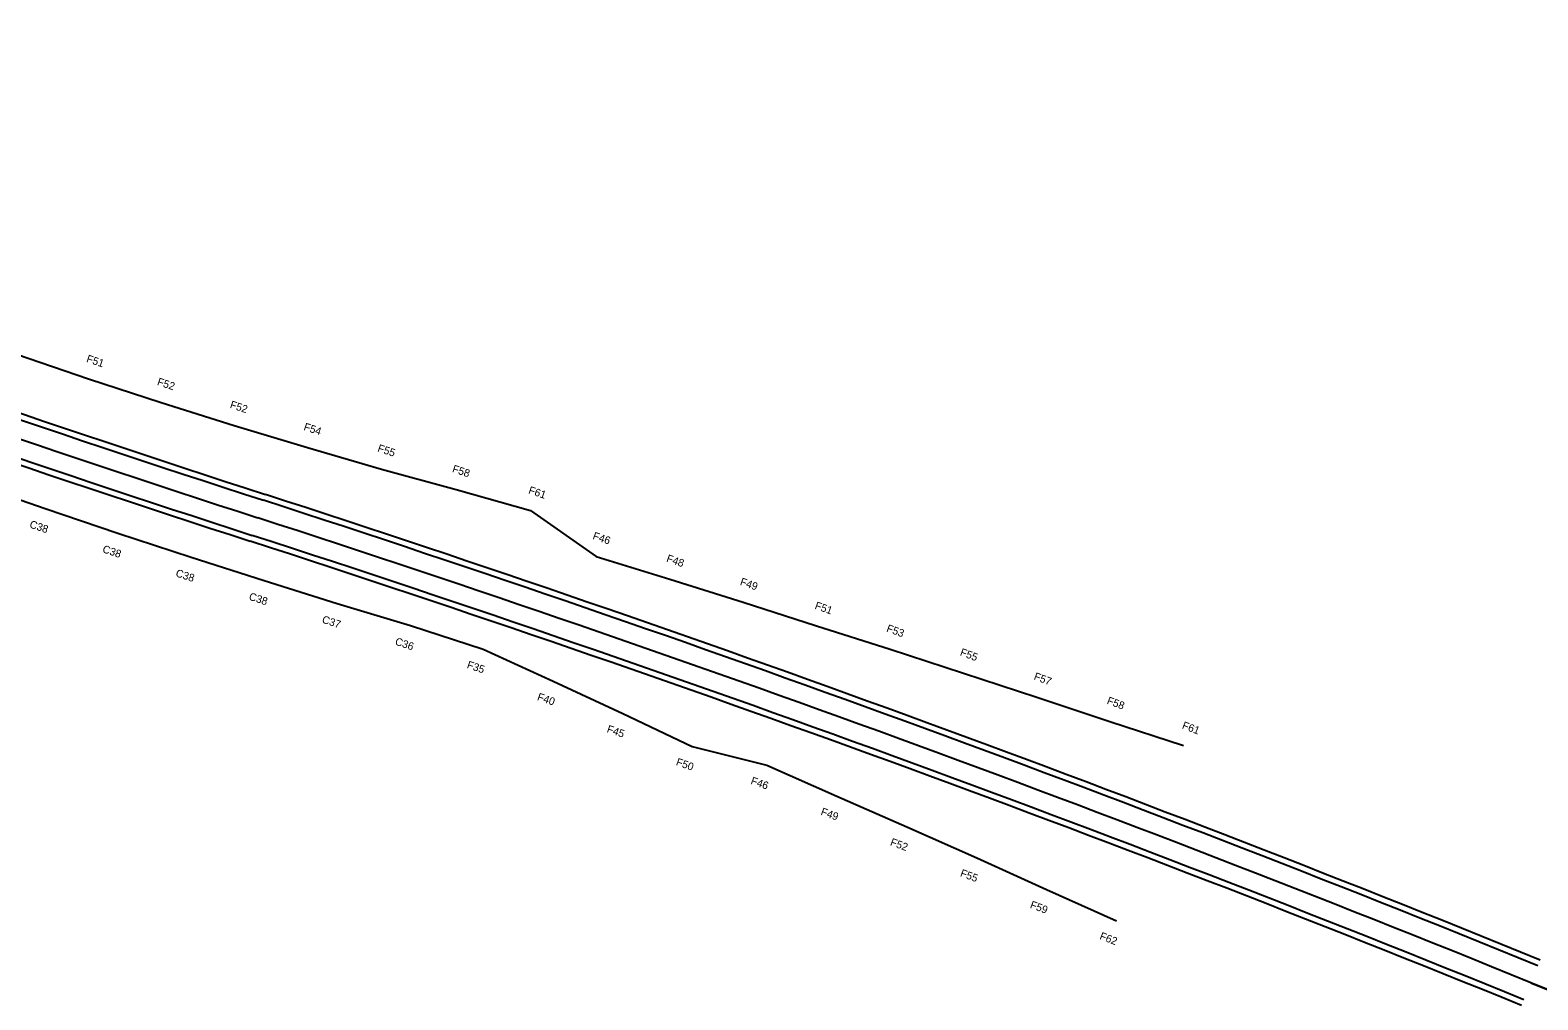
# Model space of a CAD drawing. Extents: x 2163527 to 2171930, y 206045 to 210376.
# Drawn here: x 2166437 to 2167420, y 208838 to 209469 of the extents above; entities that cross this region are included whole.
import ezdxf

# ---------------------------------------------------------------- set-up
doc = ezdxf.new("R2010")
doc.units = 0
for name, color, linetype in [('Default', 7, 'Continuous'), ('RD_PD_CstnLmt', 7, 'Continuous'), ('RD_PD_TX_CstnLmt', 7, 'Continuous')]:
    doc.layers.add(name, color=color, linetype=linetype)

msp = doc.modelspace()

# ---------------------------------------------------------------- linework, layer by layer
at = {"layer": 'Default'}
for p, q in [((2170316.55, 207666.95), (2167415.27, 208848.65)), ((2167415.27, 208848.65), (2170458.15, 207609.28))]:
    msp.add_line(p, q, dxfattribs=at)
for centre, radius, start, end in [((2170282.56, 220567.81), 11988, 247.838824, 252.056631), ((2170282.56, 220567.81), 11988, 247.838824, 252.056631), ((2170282.56, 220567.81), 11984, 247.838824, 252.056631), ((2170282.56, 220567.81), 12000, 247.838824, 252.056631), ((2170282.56, 220567.81), 12000, 247.838824, 252.056631), ((2170282.56, 220567.81), 12012, 247.838824, 252.056631), ((2170282.56, 220567.81), 12012, 247.838824, 252.056631), ((2170282.56, 220567.81), 12016, 247.838824, 252.056631), ((2162888.71, 197735.13), 12016, 67.838824, 72.056631), ((2162888.71, 197735.13), 12012, 67.838824, 72.056631), ((2162888.71, 197735.13), 12012, 67.838824, 72.056631), ((2162888.71, 197735.13), 12000, 67.838824, 72.056631), ((2162888.71, 197735.13), 12000, 67.838824, 72.056631), ((2162888.71, 197735.13), 11988, 67.838824, 72.056631), ((2162888.71, 197735.13), 11988, 67.838824, 72.056631), ((2162888.71, 197735.13), 11984, 67.838824, 72.056631)]:
    msp.add_arc(centre, radius, start, end, dxfattribs=at)
at = {"layer": 'RD_PD_CstnLmt'}
for p, q in [((2166428.26, 209258.13), (2166475.34, 209241.94)), ((2166475.34, 209241.94), (2166522.69, 209226.55)), ((2166522.69, 209226.55), (2166570.19, 209211.63)), ((2166570.19, 209211.63), (2166618.02, 209197.27)), ((2166618.02, 209197.27), (2166666.28, 209183.26)), ((2166666.28, 209183.26), (2166714.78, 209169.91)), ((2166399.6, 209174.02), (2166446.98, 209157.56)), ((2166714.78, 209169.91), (2166763.24, 209156.36)), ((2166446.98, 209157.56), (2166494.48, 209141.45)), ((2166763.24, 209156.36), (2166806.04, 209126.29)), ((2166494.48, 209141.45), (2166542.14, 209125.82)), ((2166542.14, 209125.82), (2166589.82, 209110.6)), ((2166806.04, 209126.29), (2166854.06, 209111.57)), ((2166589.82, 209110.6), (2166637.37, 209095.63)), ((2166854.06, 209111.57), (2166901.96, 209096.45)), ((2166637.37, 209095.63), (2166685.12, 209081.26)), ((2166901.96, 209096.45), (2166949.81, 209081.16)), ((2166685.12, 209081.26), (2166732.54, 209065.85)), ((2166949.81, 209081.16), (2166997.68, 209065.88)), ((2166732.54, 209065.85), (2166778.1, 209045.05)), ((2166997.68, 209065.88), (2167045.49, 209050.38)), ((2167045.49, 209050.38), (2167093.27, 209034.76)), ((2166778.1, 209045.05), (2166823.56, 209024.06)), ((2167093.27, 209034.76), (2167140.97, 209018.89)), ((2166823.56, 209024.06), (2166868.78, 209002.51)), ((2167140.97, 209018.89), (2167188.77, 209003.21)), ((2166868.78, 209002.51), (2166917.3, 208990.32)), ((2166917.3, 208990.32), (2166962.96, 208970.14)), ((2166962.96, 208970.14), (2167008.67, 208950.15)), ((2167008.67, 208950.15), (2167054.26, 208929.93)), ((2167054.26, 208929.93), (2167099.69, 208909.33)), ((2167099.69, 208909.33), (2167145.14, 208888.89))]:
    msp.add_line(p, q, dxfattribs=at)

# ---------------------------------------------------------------- texts
at = {"layer": 'RD_PD_TX_CstnLmt'}
for s, rotation, p in [('F51', 341.41981, (2166473.51, 209253.11)), ('F52', 341.65854, (2166519.62, 209238.11)), ('F52', 341.89727, (2166567.07, 209223.17)), ('F54', 341.97726, (2166615.11, 209208.74)), ('F55', 341.73852, (2166663.27, 209194.79)), ('F58', 341.49979, (2166711.91, 209181.42)), ('F61', 341.26106, (2166761.59, 209167.48)), ('C38', 341.41981, (2166436.41, 209145.28)), ('F46', 341.02233, (2166803.47, 209137.75)), ('C38', 341.65854, (2166483.96, 209129.13)), ('F48', 340.78359, (2166851.48, 209123.07)), ('C38', 341.89727, (2166531.68, 209113.46)), ('F49', 340.54486, (2166899.48, 209107.93)), ('C38', 341.97726, (2166579.38, 209098.23)), ('F51', 340.30613, (2166948.2, 209092.36)), ('C37', 341.73852, (2166627.04, 209083.24)), ('F53', 340.0674, (2166994.89, 209077.53)), ('C36', 341.49979, (2166674.63, 209068.95)), ('F55', 339.82866, (2167042.86, 209062)), ('F35', 341.26106, (2166721.47, 209053.77)), ('F57', 339.58993, (2167090.94, 209046.29)), ('F40', 341.02233, (2166767.32, 209032.89)), ('F58', 339.3512, (2167138.53, 209030.5)), ('F45', 340.78359, (2166812.66, 209011.97)), ('F61', 339.11247, (2167187.53, 209014.38)), ('F50', 340.54486, (2166857.75, 208990.5)), ('F46', 340.30613, (2166906.44, 208978.27)), ('F49', 340.0674, (2166952.06, 208958.14)), ('F52', 339.82866, (2166997.34, 208938.33)), ('F55', 339.58993, (2167042.96, 208918.13)), ('F59', 339.3512, (2167088.48, 208897.52)), ('F62', 339.11247, (2167133.82, 208877.16))]:
    msp.add_text(s, height=5, rotation=rotation, dxfattribs=at).set_placement(p)

doc.saveas('drawing.dxf')
